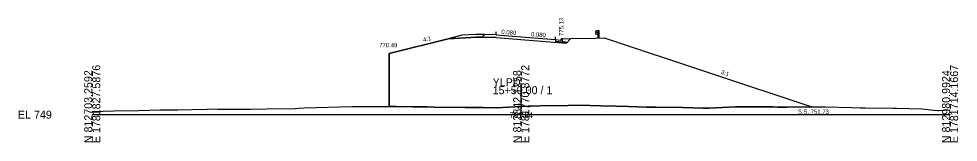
# Model space of a CAD drawing. Extents: x -26 to 353, y -10 to 9080.
# Drawn here: x -25.7 to 302.8, y 5490.3 to 5533.7 of the extents above; entities that cross this region are included whole.
import ezdxf

# ---------------------------------------------------------------- set-up
doc = ezdxf.new("R2010")
doc.units = 0
for name, color, linetype in [('Exist Cross Section Cell', 7, 'Continuous'), ('Exist XS Center Line Elevation Label', 7, 'Continuous'), ('Exist XS Ground Line', 7, 'Continuous'), ('Prop XS Ditch Slope Text', 7, 'Continuous'), ('Prop XS Dump Level', 7, 'Continuous'), ('Prop XS Earthwork Shape', 7, 'Continuous'), ('Prop XS EOT Tick Mark', 7, 'Continuous'), ('Prop XS Finish Grade', 7, 'Continuous'), ('Prop XS Finish Grade CurbGutter', 7, 'Continuous'), ('Prop XS Finish Grade Earthwork', 7, 'Continuous'), ('Prop XS Finish Grade Paved Shoulder', 7, 'Continuous'), ('Prop XS Finish Grade Pavement', 7, 'Continuous'), ('Prop XS Guardrail', 7, 'Continuous'), ('Prop XS Hydro Elevations', 7, 'Continuous'), ('Prop XS Pvmt Edge Slope', 7, 'Continuous'), ('Prop XS SE Text', 7, 'Continuous'), ('Prop XS Side Slope Text', 7, 'Continuous'), ('Prop XS SS Elevation Text', 7, 'Continuous'), ('Prop XS Subgrade CurbGutter', 7, 'Continuous'), ('Prop XS Subgrade Earthwork', 7, 'Continuous'), ('Scratch_Level_3', 7, 'Continuous')]:
    doc.layers.add(name, color=color, linetype=linetype)

msp = doc.modelspace()

# ---------------------------------------------------------------- linework, layer by layer
at = {"layer": 'Exist Cross Section Cell'}
for p, q in [((150, 5500), (150, 5509.98)), ((0, 5500), (150, 5500)), ((150, 5500), (300, 5500))]:
    msp.add_line(p, q, dxfattribs=at)
at = {"layer": 'Exist XS Ground Line'}
for p, q in [((150, 5502.84), (152.41, 5502.94)), ((152.41, 5502.94), (153.49, 5502.97)), ((153.49, 5502.97), (156.55, 5503.07)), ((156.55, 5503.07), (166.43, 5503.2)), ((166.43, 5503.2), (170.28, 5503.33)), ((170.28, 5503.33), (177.89, 5503.1)), ((177.89, 5503.1), (183.26, 5502.98)), ((183.26, 5502.98), (187.55, 5502.86)), ((0, 5501.14), (7.5, 5501.38)), ((7.5, 5501.38), (16.22, 5501.51)), ((16.22, 5501.51), (23.64, 5501.74)), ((23.64, 5501.74), (29.91, 5501.71)), ((29.91, 5501.71), (40.08, 5501.97)), ((40.08, 5501.97), (41.2, 5502)), ((41.2, 5502), (43.95, 5501.97)), ((43.95, 5501.97), (51.82, 5501.94)), ((51.82, 5501.94), (55.48, 5501.96)), ((55.48, 5501.96), (60.93, 5502.06)), ((60.93, 5502.06), (70.82, 5502.22)), ((70.82, 5502.22), (72.22, 5502.26)), ((72.22, 5502.26), (74.08, 5502.38)), ((74.08, 5502.38), (90.77, 5502.85)), ((90.77, 5502.85), (102.81, 5502.85)), ((102.81, 5502.85), (106.29, 5502.81)), ((106.29, 5502.81), (112.18, 5502.78)), ((112.18, 5502.78), (117.12, 5502.73)), ((117.12, 5502.73), (119.61, 5502.67)), ((119.61, 5502.67), (130.43, 5502.5)), ((130.43, 5502.5), (136.57, 5502.52)), ((136.57, 5502.52), (141.42, 5502.45)), ((141.42, 5502.45), (150, 5502.84)), ((187.55, 5502.86), (193.83, 5502.66)), ((193.83, 5502.66), (197.12, 5502.6)), ((197.12, 5502.6), (206.56, 5502.49)), ((206.56, 5502.49), (213.61, 5502.26)), ((213.61, 5502.26), (214.61, 5502.26)), ((214.61, 5502.26), (215.62, 5502.3)), ((215.62, 5502.3), (224.99, 5502.76)), ((224.99, 5502.76), (238.01, 5502.74)), ((238.01, 5502.74), (239.77, 5502.66)), ((239.77, 5502.66), (242.94, 5502.68)), ((242.94, 5502.68), (251.34, 5502.73)), ((251.34, 5502.73), (256.46, 5502.69)), ((256.46, 5502.69), (265.68, 5502.46)), ((265.68, 5502.46), (268.7, 5502.43)), ((268.7, 5502.43), (270.47, 5502.36)), ((270.47, 5502.36), (280.03, 5502.3)), ((280.03, 5502.3), (280.49, 5502.31)), ((280.49, 5502.31), (281.29, 5502.29)), ((281.29, 5502.29), (290.08, 5502.03)), ((290.08, 5502.03), (294.31, 5501.63)), ((294.31, 5501.63), (295.62, 5501.51)), ((295.62, 5501.51), (296.12, 5501.46)), ((296.12, 5501.46), (300, 5501.7))]:
    msp.add_line(p, q, dxfattribs=at)
at = {"layer": 'Prop XS Dump Level'}
for p, q in [((141.3, 5528.02), (150, 5527.33)), ((150, 5527.33), (162, 5526.37))]:
    msp.add_line(p, q, dxfattribs=at)
at = {"layer": 'Prop XS Earthwork Shape'}
msp.add_lwpolyline([(165.84, 5525.14), (167.39, 5526.69), (176, 5526.87), (179, 5526.93), (251.6, 5502.73), (251.34, 5502.73), (242.94, 5502.68), (239.77, 5502.66), (238.01, 5502.74), (224.99, 5502.76), (215.62, 5502.3), (214.61, 5502.26), (213.61, 5502.26), (206.56, 5502.49), (197.12, 5502.6), (193.83, 5502.66), (187.55, 5502.86), (183.26, 5502.98), (177.89, 5503.1), (170.28, 5503.33), (166.43, 5503.2), (156.55, 5503.07), (153.49, 5502.97), (152.41, 5502.94), (150, 5502.84), (141.42, 5502.45), (136.57, 5502.52), (130.43, 5502.5), (119.61, 5502.67), (117.12, 5502.73), (112.18, 5502.78), (106.29, 5502.81), (103.81, 5502.84), (103.81, 5521.49), (124.47, 5526.65), (134.32, 5527.25), (136.4, 5527.2), (141.25, 5527.11), (149.93, 5526.41)], close=True, dxfattribs=at)
at = {"layer": 'Prop XS EOT Tick Mark'}
for p, q in [((141.3, 5528.02), (141.3, 5529.02)), ((162, 5526.37), (162, 5527.37))]:
    msp.add_line(p, q, dxfattribs=at)
at = {"layer": 'Prop XS Finish Grade'}
for p, q in [((129.3, 5527.86), (124.47, 5526.65)), ((134.3, 5528.16), (129.3, 5527.86)), ((137.3, 5528.1), (134.3, 5528.16)), ((164.5, 5526.63), (167.39, 5526.69))]:
    msp.add_line(p, q, dxfattribs=at)
at = {"layer": 'Prop XS Finish Grade CurbGutter'}
for p, q in [((162, 5526.37), (163.75, 5526.16)), ((163.75, 5526.16), (163.87, 5526.18)), ((163.87, 5526.18), (163.97, 5526.27)), ((163.97, 5526.27), (164.03, 5526.52)), ((164.03, 5526.52), (164.12, 5526.61)), ((164.25, 5526.63), (164.12, 5526.61)), ((164.5, 5526.63), (164.25, 5526.63))]:
    msp.add_line(p, q, dxfattribs=at)
at = {"layer": 'Prop XS Finish Grade Earthwork'}
for p, q in [((124.47, 5526.65), (103.81, 5521.49)), ((167.39, 5526.69), (176, 5526.87)), ((176, 5526.87), (179, 5526.93)), ((179, 5526.93), (251.6, 5502.73)), ((103.81, 5521.49), (103.81, 5502.84))]:
    msp.add_line(p, q, dxfattribs=at)
at = {"layer": 'Prop XS Finish Grade Paved Shoulder'}
msp.add_line((141.3, 5528.02), (137.3, 5528.1), dxfattribs=at)
at = {"layer": 'Prop XS Finish Grade Pavement'}
for p, q in [((141.3, 5528.02), (150, 5527.33)), ((150, 5527.33), (162, 5526.37))]:
    msp.add_line(p, q, dxfattribs=at)
at = {"layer": 'Prop XS Guardrail'}
for p, q in [((176.03, 5529.25), (176, 5529.19)), ((176.32, 5529.45), (176.03, 5529.25)), ((176.82, 5529.45), (176.32, 5529.45)), ((177.32, 5529.45), (176.82, 5529.45)), ((176.82, 5529.45), (176.82, 5526.95)), ((177.32, 5526.95), (177.32, 5529.45)), ((176, 5529.19), (176.03, 5529.13)), ((176.03, 5528.63), (176, 5528.57)), ((176, 5528.57), (176.03, 5528.51)), ((176.03, 5529.13), (176.32, 5528.93)), ((176.32, 5528.83), (176.03, 5528.63)), ((176.03, 5528.51), (176.32, 5528.31)), ((176.32, 5528.93), (176.32, 5528.83)), ((176.32, 5528.31), (176.82, 5528.31))]:
    msp.add_line(p, q, dxfattribs=at)
at = {"layer": 'Prop XS Pvmt Edge Slope'}
for p, q in [((137.3, 5528.1), (136.4, 5527.2)), ((164.5, 5525.59), (165.5, 5525.51)), ((165.5, 5525.51), (165.84, 5525.14))]:
    msp.add_line(p, q, dxfattribs=at)
at = {"layer": 'Prop XS Subgrade CurbGutter'}
for p, q in [((162, 5526.37), (162, 5525.79)), ((164.5, 5525.59), (164.5, 5526.63)), ((162, 5525.79), (164.5, 5525.59))]:
    msp.add_line(p, q, dxfattribs=at)
at = {"layer": 'Prop XS Subgrade Earthwork'}
for p, q in [((134.32, 5527.25), (124.47, 5526.65)), ((136.4, 5527.2), (134.32, 5527.25)), ((141.25, 5527.11), (136.4, 5527.2)), ((141.25, 5527.11), (149.93, 5526.41)), ((149.93, 5526.41), (165.84, 5525.14)), ((165.84, 5525.14), (167.39, 5526.69))]:
    msp.add_line(p, q, dxfattribs=at)
at = {"layer": 'Scratch_Level_3'}
for p, q in [((129.3, 5527.86), (124.47, 5526.65)), ((124.47, 5526.65), (134.32, 5527.25)), ((134.3, 5528.16), (129.3, 5527.86)), ((137.3, 5528.1), (134.3, 5528.16)), ((134.32, 5527.25), (136.4, 5527.2)), ((136.4, 5527.2), (137.3, 5528.1))]:
    msp.add_line(p, q, dxfattribs=at)

# ---------------------------------------------------------------- texts
at = {"layer": 'Exist Cross Section Cell'}
for s, p in [('E 1781827.5876', (2.8, 5490)), ('E 1781770.8772', (152.8, 5490)), ('E 1781714.1667', (302.8, 5490)), ('N 812703.2592', (0, 5490)), ('N 812842.1258', (150, 5490)), ('N 812980.9924', (300, 5490))]:
    msp.add_text(s, height=2.8, rotation=90, dxfattribs=at).set_placement(p)
for s, p in [('YLPD', (140, 5509.98)), ('15+50.00 / 1', (140, 5507.18)), ('EL 749', (-26, 5498.6))]:
    msp.add_text(s, height=2.8, dxfattribs=at).set_placement(p)
at = {"layer": 'Exist XS Center Line Elevation Label'}
msp.add_text('751.84', height=2, dxfattribs=at).set_placement((145.96, 5498.84))
at = {"layer": 'Prop XS Ditch Slope Text'}
msp.add_text('770.49', height=1.5, dxfattribs=at).set_placement((100.35, 5523.65))
at = {"layer": 'Prop XS Dump Level'}
msp.add_text('Case4', height=0.04, dxfattribs=at).set_placement((129.3, 5527.82))
at = {"layer": 'Prop XS Hydro Elevations'}
msp.add_text('775.13', height=1.5, rotation=90, dxfattribs=at).set_placement((164.75, 5527.63))
at = {"layer": 'Prop XS SE Text'}
for p in [(143.03, 5528.38), (153.38, 5527.56)]:
    msp.add_text('0.080', height=1.5, rotation=355.4261, dxfattribs=at).set_placement(p)
at = {"layer": 'Prop XS Side Slope Text'}
for s, rotation, p in [('4:1', 14.0362, (115.88, 5525.51)), ('3:1', 340.8635, (219.71, 5514.4))]:
    msp.add_text(s, height=1.5, rotation=rotation, dxfattribs=at).set_placement(p)
at = {"layer": 'Prop XS SS Elevation Text'}
msp.add_text('S.S. 751.73', height=1.5, dxfattribs=at).set_placement((246.77, 5500.31))

doc.saveas('drawing.dxf')
